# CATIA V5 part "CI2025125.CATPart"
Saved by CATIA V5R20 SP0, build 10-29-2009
Part number: CI2025125
Bounding box of the stored display mesh (mm): x -24 to 24, y -18.97 to 159.5, z -32.903 to 26.909
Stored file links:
  C:\Users\Raffaele\Desktop\3D X SITO CF\BOLEX\19-INCLINED ASSEMBLY REF_CI\CI2025125.CATPart

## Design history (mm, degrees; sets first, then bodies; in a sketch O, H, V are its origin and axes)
Set1
  DatumSurface1 to DatumSurface16 "MANIFOLD_SOLID_BREP #389"
  DatumSurface17 to DatumSurface39 "MANIFOLD_SOLID_BREP #1134"
Body1 (main body)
